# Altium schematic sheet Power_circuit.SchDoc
size A4; SheetNumber: 1; SheetTotal: 3; SPICEModelCacheATQZOLGF: <root> / <DocumentId>ATQZOLGF</DocumentId> / <CacheFrame Number="0"> / <Model Name="emk316bbj476_l-t" Kind="CKT"> / <Text>* EMK316BBJ476_L-T     SPICE MODEL  ( General Type ) / *-------------------------------------------------------------------------------------------------------- / * Model Generated by TAIYO YUDEN Corporation (http://www.ty-top.com) / * Version 1.0 / * TAIYO YUDEN Control No. 170508_160201 / * Copyright(c) 2016 TAIYO YUDEN CO.,LTD. All Rights Reserved. / *-------------------------------------------------------------------------------------------------------- / * / * Products Name : Multilayer Ceramic Capacitors / * / * Characteristics : / *     Capacitance : 47 uF , Rated Voltage : 16V , TCC : X5R / *     Case Size : 3.2 x 1.6 / 0.126 x 0.063 [mm/inch] , Thickness : 1.6 / 0.063 [mm/inch] / *     (Conditions: Temperature = 25 degC , DC Bias Current/Voltage = 0A / 0V) / * / * Frequency Range : 40Hz - 3GHz / * / * External Node Assignments : / * / *  1  o---¦ ¦---o  2 / * / *-------------------------------------------------------------------------------------------------------- / .SubCkt EMK316BBJ476_L-T 1 2 / **************************** / C0 1 110 39.785u / Cm 1 101 2.9335u / C1 101 102 3.2986u / Rc1 101 102 158.48 / C2 102 103 2.1731u / Rc2 102 103 15.988 / C3 103 110 0.1168u / Rc3 103 110 3.1602 / C2m 1 301 5.1294u / C21 301 302 6.2048u / Rc21 301 302 908.8 / C22 302 303 7.0189u / Rc22 302 303 251.89 / C23 303 304 10.585u / Rc23 303 304 121.1 / C24 304 305 1.745u / Rc24 304 305 66.669 / C25 305 306 2.0483u / Rc25 305 306 43.084 / C26 306 307 0.83506u / Rc26 306 307 3.353 / C27 307 308 0.20912u / Rc27 307 308 8.5674 / C28 308 309 0.87358u / Rc28 308 309 1.8455 / C29 309 110 0.051814u / Rc29 309 110 3.3713 / Rp0 1 110 2.12765957446809Meg / L0 110 120 0.23607n / Lm 120 130 0.28508n / L1 120 121 0.18542n / RL1 121 130 7.9423 / L2 120 122 0.18844n / RL2 122 130 0.11704 / L3 120 123 2.5471n / RL3 123 130 0.25894 / CR 120 124 7.083u / LR 124 125 0.6729n / RR 125 130 10.406m / CL 130 140 0.7161p / LL 130 140 0.23733n / RL 130 140 37.362 / Rs 140 2 2.1493m / **************************** / .ends EMK316BBJ476_L-T</Text> / </Model> / </CacheFrame> / </root>
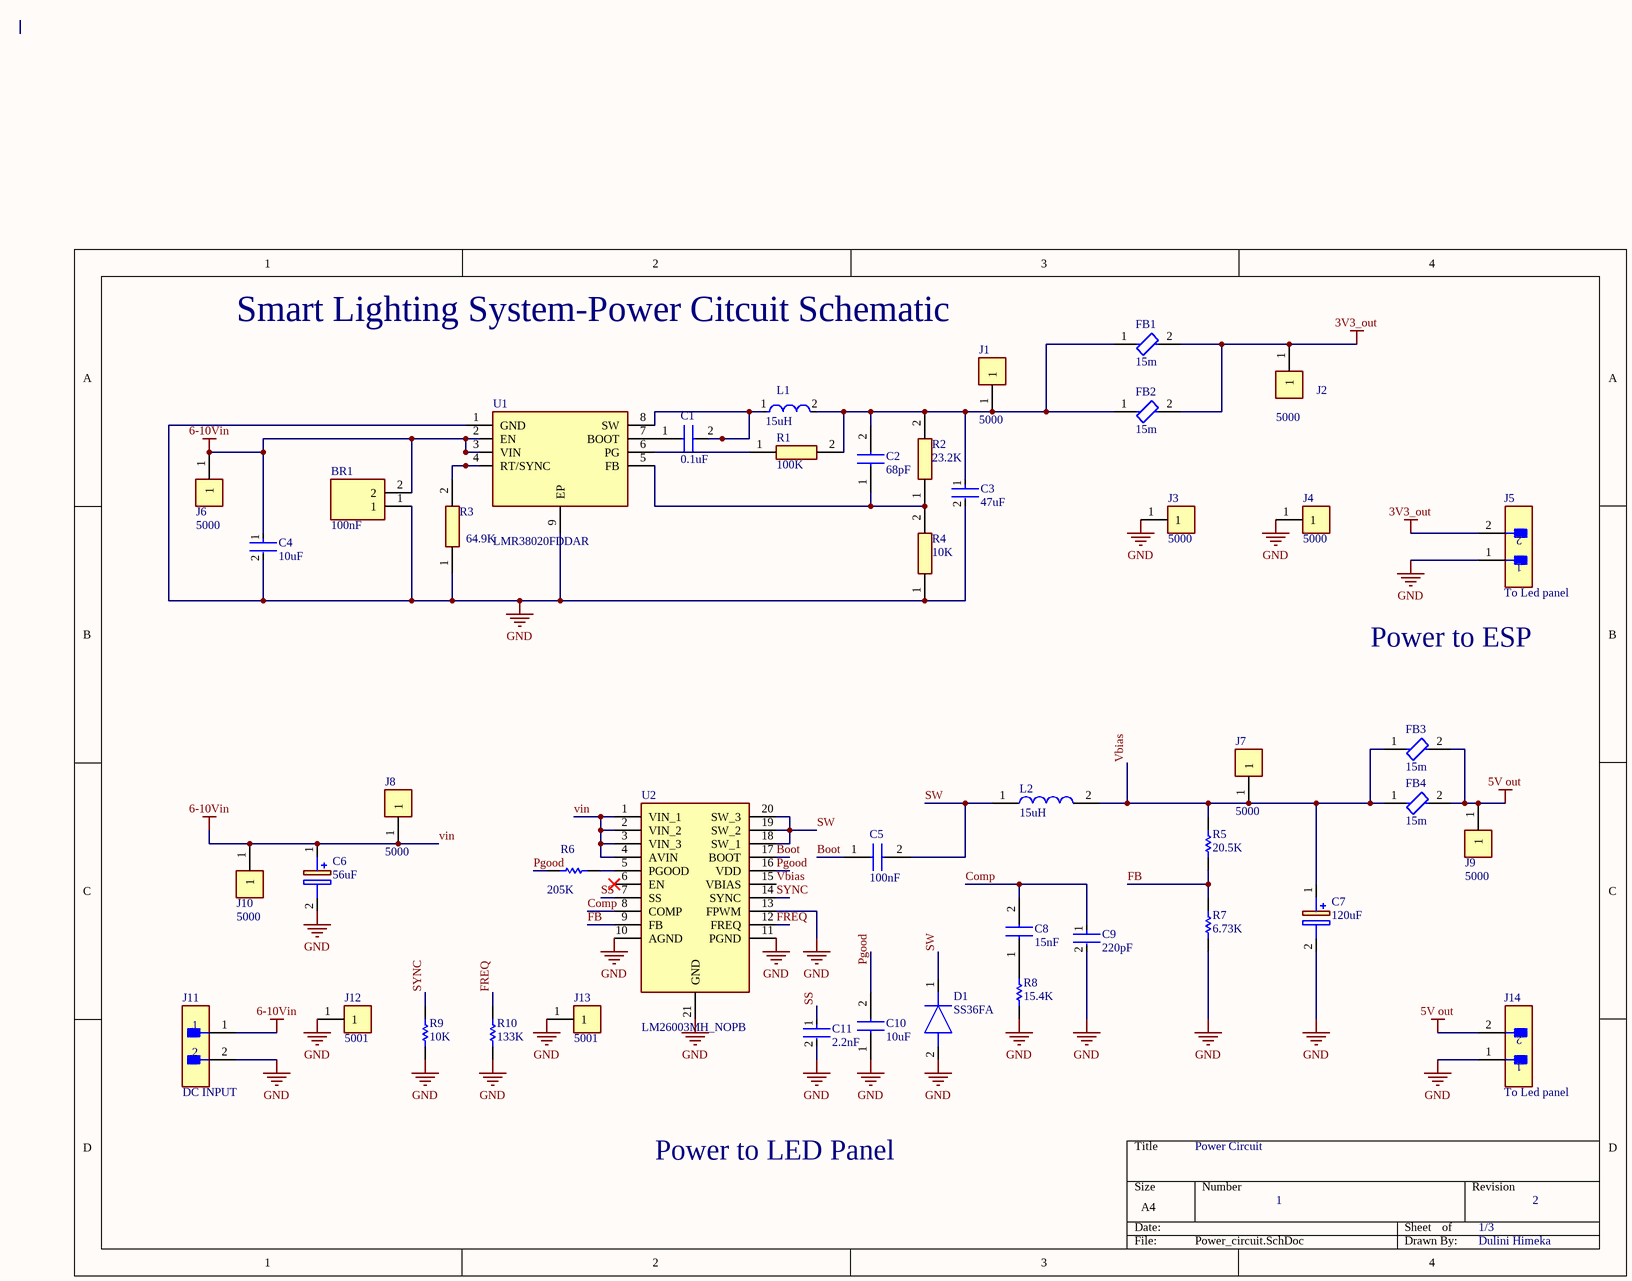
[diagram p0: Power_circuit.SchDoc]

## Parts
BR1  100nF  [CAPC3216X140N]
C1  0.1uF  [CAPC3216X200N]
C2  68pF  [CAPC3216X90N]
C3  47uF  [FP-1206-L_3_2_0_3-W_1_6_0-MFG]
C4  10uF  [FP-GRM31C-0_2-e0_3_0_8-MFG]
C5  100nF  [CAPC2013X94N]
C6  56uF  [EEHZA1E101XP]
C7  120uF  [10SVPC120M]
C8  15nF  [C2012_Commercial]
C9  220pF  [FP-CL21-IPC_B]
C10  10uF  [CAPC3216X170N]
C11  2.2nF  [FP-CL21-IPC_C]
D1  SS36FA  [SODFL3618X143N]
FB1  15m  [FP-BLM21-0_2-t0_85-e0_5-d-IPC_B]
FB2  15m  [FP-BLM21-0_2-t0_85-e0_5-d-IPC_B]
FB3  15m  [FP-BLM21-0_2-t0_85-e0_5-d-IPC_B]
FB4  15m  [FP-BLM21-0_2-t0_85-e0_5-d-IPC_B]
J1  5000  [FP-5000-MFG]
J2  5000  [FP-5000-MFG]
J3  5000  [FP-5000-MFG]
J4  5000  [FP-5000-MFG]
J5  To Led panel  [FP-61900211121-MFG]
J6  5000  [FP-5000-MFG]
J7  5000  [FP-5000-MFG]
J8  5000  [FP-5000-MFG]
J9  5000  [FP-5000-MFG]
J10  5000  [FP-5000-MFG]
J11  DC INPUT  [FP-61900211121-MFG]
J12  5001  [FP-5001-MFG]
J13  5001  [FP-5001-MFG]
J14  To Led panel  [FP-61900211121-MFG]
L1  15uH  [FP-SRR1260-MFG]
L2  15uH  [INDPM7366X300N]
R1  100K  [RESC3116X65N]
R2  23.2K  [ERJ8ENF1000V]
R3  64.9K  [ERJ8ENF1000V]
R4  10K  [ERJ8ENF1000V]
R5  20.5K  [RESC2013X70X40NL20T20]
R6  205K  [RESC3216X60X45NL10T20]
R7  6.73K  [RESC2013X60X35NL10T20]
R8  15.4K  [RESC3216X70X50LL05T20]
R9  10K  [RESC3116X65X40ML10T20]
R10  133K  [RESC3216X70X50LL20T25]
U1  LMR38020FDDAR  [SOIC127P600X170-9N]
U2  LM26003MH_NOPB  [SOP65P640X110-21N]

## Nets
3V3_out: FB1.2 FB2.2 J2.1 J5.2
5V out: FB3.2 FB4.2 J9.1 J14.2
GND: BR1.1 C3.2 C4.2 C6.2(-) C7.2(-) C9.2 C10.1 C11.2 D1.2(A) J3.1 J4.1 J5.1 J11.2 J12.1 J13.1 J14.1 R3.1 R4.1 R7.1 R8.1 R9.1 R10.2 U1.1(GND) U1.9(EP) U2.10(AGND) U2.11(PGND) U2.13(FPWM) U2.21(GND)
vin: BR1.2 C4.1 C6.1(+) J6.1 J8.1 J10.1 J11.1 U1.2(EN) U1.3(VIN) U2.1(VIN_1) U2.2(VIN_2) U2.3(VIN_3) U2.4(AVIN)  [also labelled 6-10Vin]
Boot: C5.1(C1) U2.17(BOOT)
Comp: C8.2 C9.1 U2.8(COMP)
FB: R5.1 R7.2 U2.9(FB)
FREQ: R10.1 U2.12(FREQ)
Pgood: C10.2 R6.1 U2.16(VDD)
SS: C11.1 U2.7(SS)
SW: C5.2(C2) D1.1(K) L2.1 U2.18(SW_1) U2.19(SW_2) U2.20(SW_3)
SYNC: R9.2 U2.14(SYNC)
Vbias: C7.1(+) FB3.1 FB4.1 J7.1 L2.2 R5.2 U2.15(VBIAS)
NetC1_1: C1.1 U1.7(BOOT)
NetC1_2: C1.2 L1.1 U1.8(SW)
NetC2_1: C2.1 R2.1 R4.2 U1.5(FB)
NetC2_2: C2.2 C3.1 FB1.1 FB2.1 J1.1 L1.2 R1.2 R2.2
NetC8_1: C8.1 R8.2
NetR1_1: R1.1 U1.6(PG)
NetR3_2: R3.2 U1.4(RT/SYNC)
NetR6_2: R6.2 U2.5(PGOOD)

Not connected (* = marked no-connect by the designer): U2 6(EN)*

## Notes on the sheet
- Smart Lighting System-Power Citcuit Schematic
- Power to ESP
- Power to LED Panel
- Power Circuit
- 1
- 1/3
- 2
- Dulini Himeka

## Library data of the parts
BR1 = C1206C104M4RECTU: Bridge Rectifier; Manufacturer_Name: KEMET
C1 = GCJ31CR72E104KXJ3L: Capacitor; Manufacturer_Name: Murata Electronics
C2 = 885012008022: Capacitor; Manufacturer_Name: Wurth Elektronik
C3 = CMP-14477-000191-2: None; Voltage Rating: 16V; Tolerance: 20%
C4 = CMP-06035-003589-1: Chip Multilayer Ceramic Capacitors for General Purpose, 1206, 10uF, X7R, 15%, 10%, 25V
C5 = 08053C104JAZ2A: Capacitor; Manufacturer_Name: AVX
C6 = EEH-ZC1E560P: Capacitor Polarised; Manufacturer_Name: Panasonic
C7 = 10SVPC120M: Capacitor Polarised; Manufacturer_Name: Panasonic
C8 = C2012C0G1H153J085AA: Capacitor; Manufacturer_Name: TDK
C9 = CMP-13271-001616-1: CL21 Series 0805 220pF 50V ±5% Tolerance C0G Multilayer Ceramic Chip Capacitor; Temperature Coefficient: 300ppm/°C
C10 = VJ1206G106KXYTW1BC: Capacitor; Manufacturer_Name: Vishay
C11 = CMP-13271-001564-1: CL21 Series 0805 2.2nF 50V ±5% Tolerance C0G Multilayer Ceramic Chip Capacitor
D1 = SS36FA: Diode; Manufacturer_Name: onsemi
FB1-FB4 = CMP-06046-001820-1: Chip Ferrite Bead, 0805, 30Ω @ 100MHz, 0.014Ω, , 4A; Impedance: 30R; Shielding: Unshielded; Max DC Current: 3A; Tolerance: 25%; DC Resistance (DCR): 14mR; Material: Steel; Number of Lines: 1; DC Resistance-Max: 15MR
J1-J4 J6-J10 = CMP-19636-000027-1: PC TEST POINT MINIATURE RED; Outside Diameter: 2.54mm; Body Material: Bronze; Number of Contacts: 1; Insulation: Insulated; Inside Diameter: 1.27mm; Hole Diameter: 1.6mm; Plating: Silver
J5 J11 J14 = CMP-1502-00584-2: CONN HEADER VERT 2POS 2.54MM; Number of Contacts: 2; Gender: Male; Current Rating: 3A; Voltage Rating: 250V; Insulation Resistance: 1GR
J12 J13 = CMP-2000-05181-2: PC TEST POINT MINIATURE BLACK; Body Material: Bronze; Plating: Silver; Inside Diameter: 1.27mm; Hole Diameter: 1.6mm; Number of Ports: 1; Outside Diameter: 2.54mm; Insulation: Insulated
L1 = CMP-2000-07146-2: FIXED IND 15UH 5A 27 MOHM SMD; Q Factor: 25; Sample Rate (Hz): 100kHz; Resistance: 27MR; Material: Steel; Inductance Tolerance: 20%; Frequency: 17.6MHz; Saturation Current: 4.6A; Core Material: Ferrite; Shielding: Shielded
L2 = SRP7028A-150M: Inductor; Manufacturer_Name: Bourns
R1 = CRM1206QFX-1003ELF: Resistor; Manufacturer_Name: Bourns
R2 = ERJ-8ENF2322V: Resistor; Manufacturer_Name: Panasonic
R3 = ERJ-8ENF6492V: Resistor; Manufacturer_Name: Panasonic
R4 = ERJ-8ENF1002V: Resistor; Manufacturer_Name: Panasonic
R5 = CMP-2001-00032-1: Manufacturer: Panasonic; Part Number: ERJ-6ENF2052V
R6 = CMP-2003-01938-1: Manufacturer: Vishay Dale; Part Number: CRCW1206205KFKEA
R7 = CMP-1659-00013-4: Chip Resistor, 10 KOhm, +/- 1%, 0.125 W, -55 to 155 degC, 0805 (2012 Metric), RoHS, Tape and Reel; Manufacturer: Yageo; Voltage Rating: 150 V
R8 = CMP-2003-00123-1: Part Number: ERJ-8ENF1542V; Manufacturer: Panasonic
R9 = CMP-1014-00623-2: Chip Resistor, 10 KOhm, +/- 1%, 0.25 W, -55 to 155 degC, 1206 (3216 Metric), RoHS, Tape and Reel; Manufacturer: Yageo; Voltage Rating: 200V; Resistance: 10KOhm; Temperature Coefficient: 100ppm/degreesC; Power Rating: 250mW
R10 = CMP-2003-04387-1: Manufacturer: Panasonic; Part Number: ERA-8AEB1333V
U1 = LMR38020FDDAR: Integrated Circuit; Manufacturer_Name: Texas Instruments
U2 = LM26003MH_NOPB: Integrated Circuit; Manufacturer_Name: Texas Instruments; Manufacturer_Part_Number: LM26003MH/NOPB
